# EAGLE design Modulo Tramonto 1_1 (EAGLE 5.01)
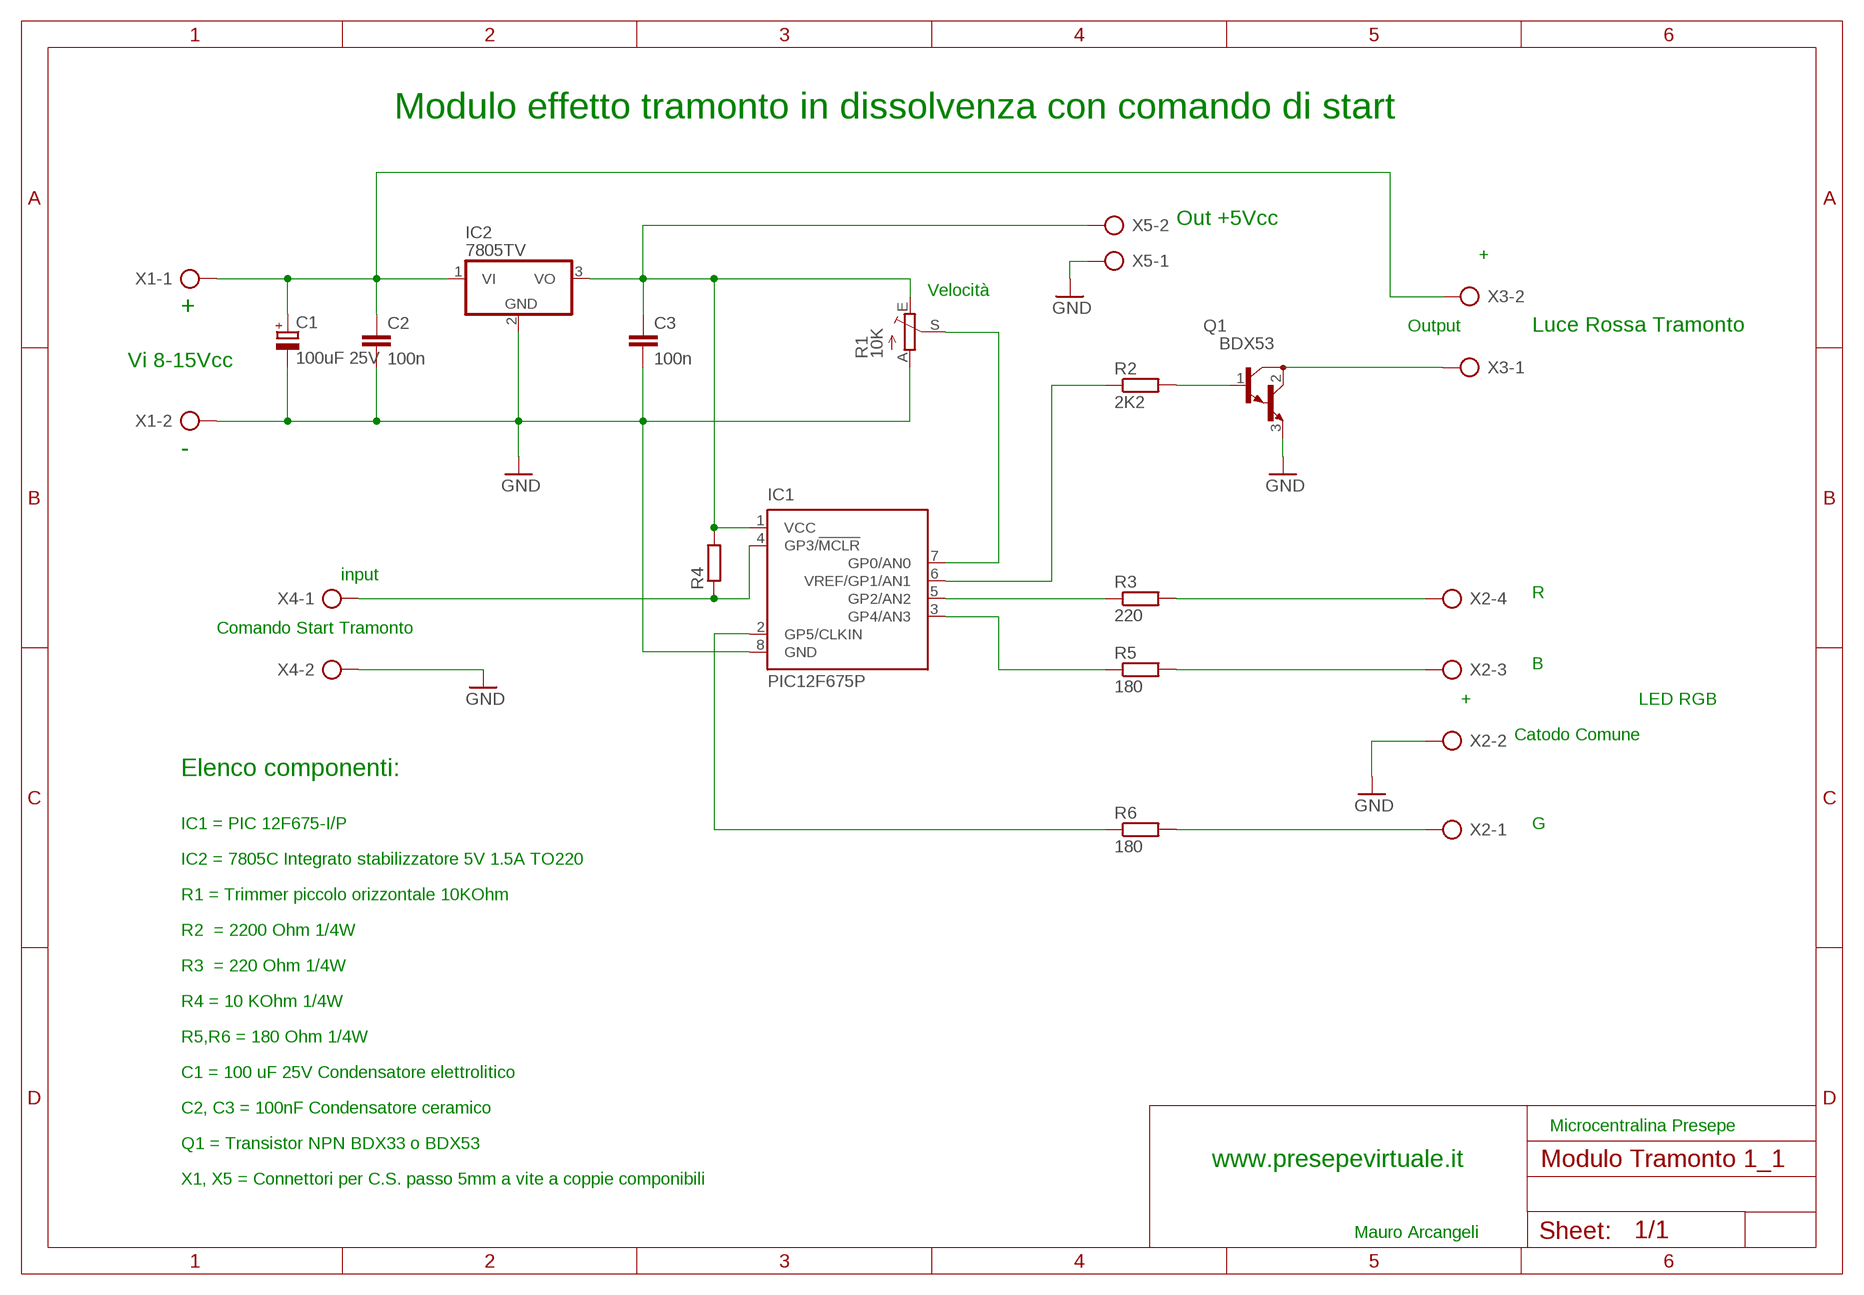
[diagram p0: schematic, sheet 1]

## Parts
C1  100uF 25V  CPOL-EUE5-5  [E5-5]
C2  100n  C-EU050-025X075  [C050-025X075]
C3  100n  C-EU050-025X075  [C050-025X075]
IC1  PIC12F675P  [DIL8]
IC2  7805TV  [TO220V]
Q1  BDX53  [TO220]
R1  10K  TRIM_EU-PT10  [PT-10]
R2  2K2  R-EU_0207/12  [0207/12]
R3  220  R-EU_0207/12  [0207/12]
R4  R-EU_0207/12  [0207/12]
R5  180  R-EU_0207/12  [0207/12]
R6  180  R-EU_0207/12  [0207/12]
X1  AK500/2  [AK500/2]
X2  AK500/4  [AK500/4]
X3  AK500/2  [AK500/2]
X4  AK500/2  [AK500/2]
X5  AK500/2  [AK500/2]

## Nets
GND: C1.- C2.2 C3.2 IC1.8(GND) IC2.2(GND) Q1.3(E) R1.A X1.2 X2.2 X4.2 X5.1
N$1: C1.+ C2.1 IC2.1(VI) X1.1 X3.2
N$2: C3.1 IC1.1(VCC) IC2.3(VO) R1.E R4.2 X5.2
N$3: IC1.2(GP5/CLKIN) R6.1
N$4: Q1.1(B) R2.2
N$5: R3.2 X2.4
N$6: Q1.2(C) X3.1
N$7: IC1.5(GP2/AN2) R3.1
N$8: IC1.7(GP0/AN0) R1.S
N$9: IC1.4(GP3/!MCLR) R4.1 X4.1
N$10: IC1.3(GP4/AN3) R5.1
N$11: R5.2 X2.3
N$12: R6.2 X2.1
N$15: IC1.6(VREF/GP1/AN1) R2.1

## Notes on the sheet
- Modulo effetto tramonto in dissolvenza con comando di start
- Out +5Vcc
- +
- Velocità
- +
- Output | Luce Rossa Tramonto
- Vi 8-15Vcc
- -
- input
- R
- Comando Start Tramonto
- B
- + | LED RGB
- Catodo Comune
- Elenco componenti:
- IC1 = PIC 12F675-I/P | G
- IC2 = 7805C Integrato stabilizzatore 5V 1.5A TO220
- R1 = Trimmer piccolo orizzontale 10KOhm
- R2  = 2200 Ohm 1/4W
- R3  = 220 Ohm 1/4W
- R4 = 10 KOhm 1/4W
- R5,R6 = 180 Ohm 1/4W
- C1 = 100 uF 25V Condensatore elettrolitico
- C2, C3 = 100nF Condensatore ceramico
- Microcentralina Presepe
- Q1 = Transistor NPN BDX33 o BDX53
- www.presepevirtuale.it
- X1, X5 = Connettori per C.S. passo 5mm a vite a coppie componibili
- Mauro Arcangeli

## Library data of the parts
C1 = rcl:CPOL-EU: POLARIZED CAPACITOR, European symbol
C2 C3 = rcl:C-EU: CAPACITOR, European symbol
IC1 = microchip:PIC12F675: 8-Pin FLASH-Based 8-Bit CMOS Microcontroller Precision Internal 4 MHz oscillator factory calibrated to ±1% Low Power Features: Standby Current: - 1 nA @ 2.0V, typical Operating Current: - 8.5&micro;A @ 32 kHz, 2.0V, typical - 100&micro;A @ 1 MHz, 2.0V, typical Watchdog Timer Current: - 300 nA @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
IC2 = linear:78*: Positive VOLTAGE REGULATOR Source: http://cache.national.com/ds/LM/LM78L05.pdf http://www.fairchildsemi.com/ds/LM/LM7805.pdf
Q1 = transistor-npn:BDX53*: NPN Darlington Transistor
R1 = pot:TRIM_EU-: POTENTIOMETER
R2-R6 = rcl:R-EU_: RESISTOR, European symbol
X1 X3-X5 = con-ptr500:AK500/2: CONNECTOR
X2 = con-ptr500:AK500/4: CONNECTOR

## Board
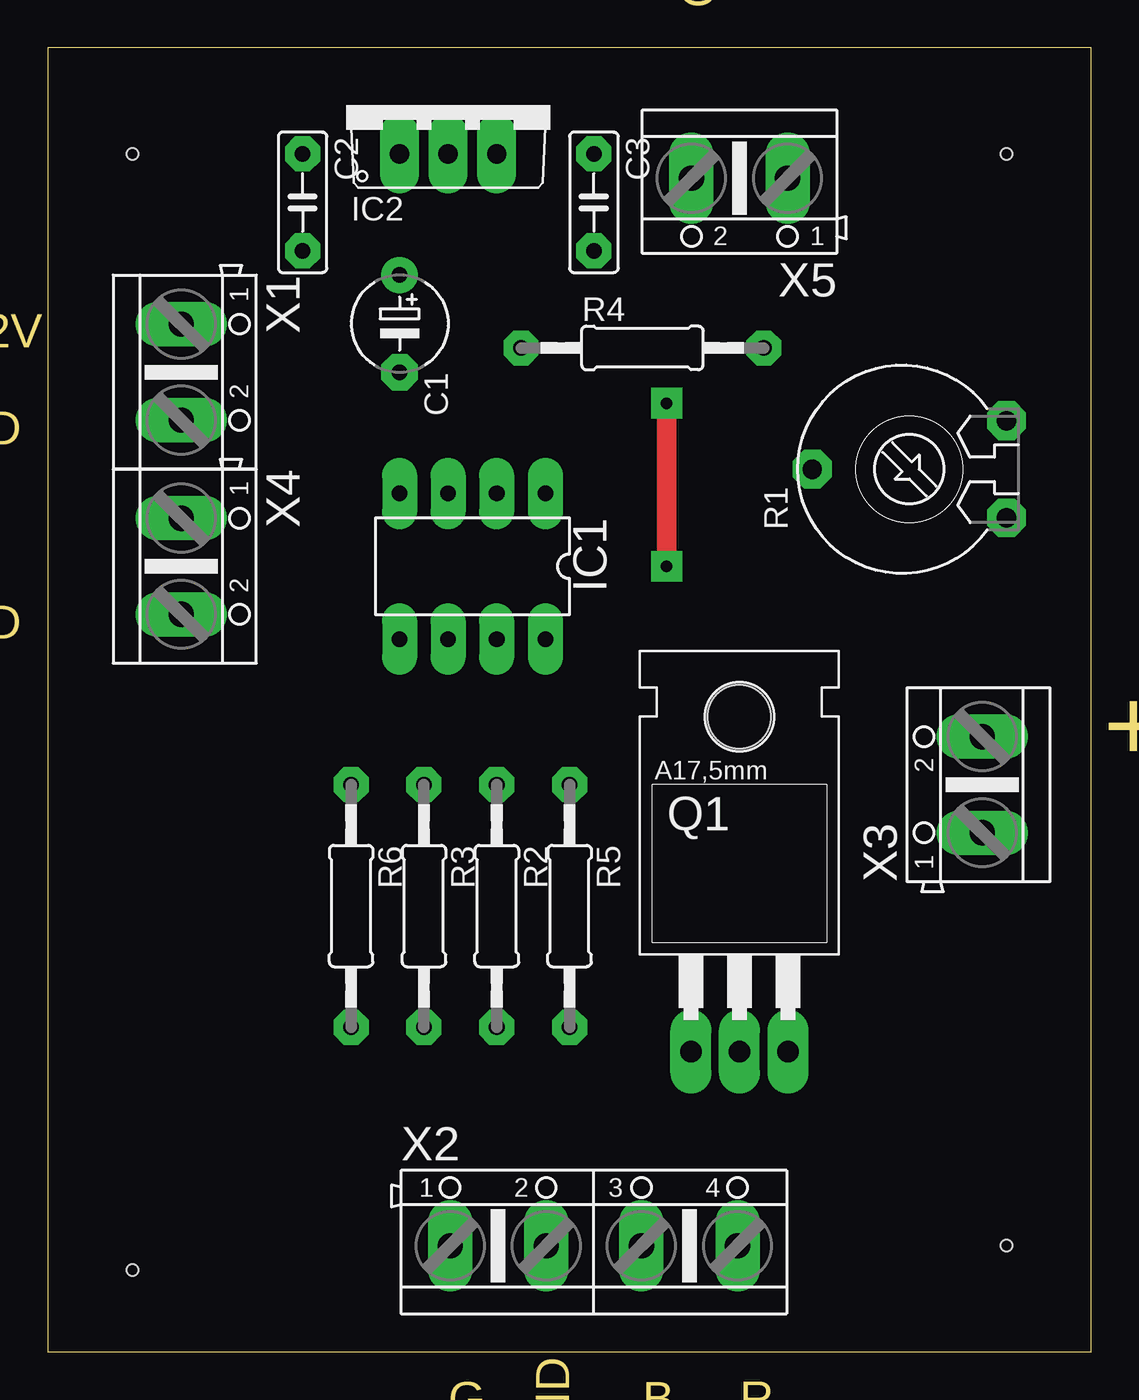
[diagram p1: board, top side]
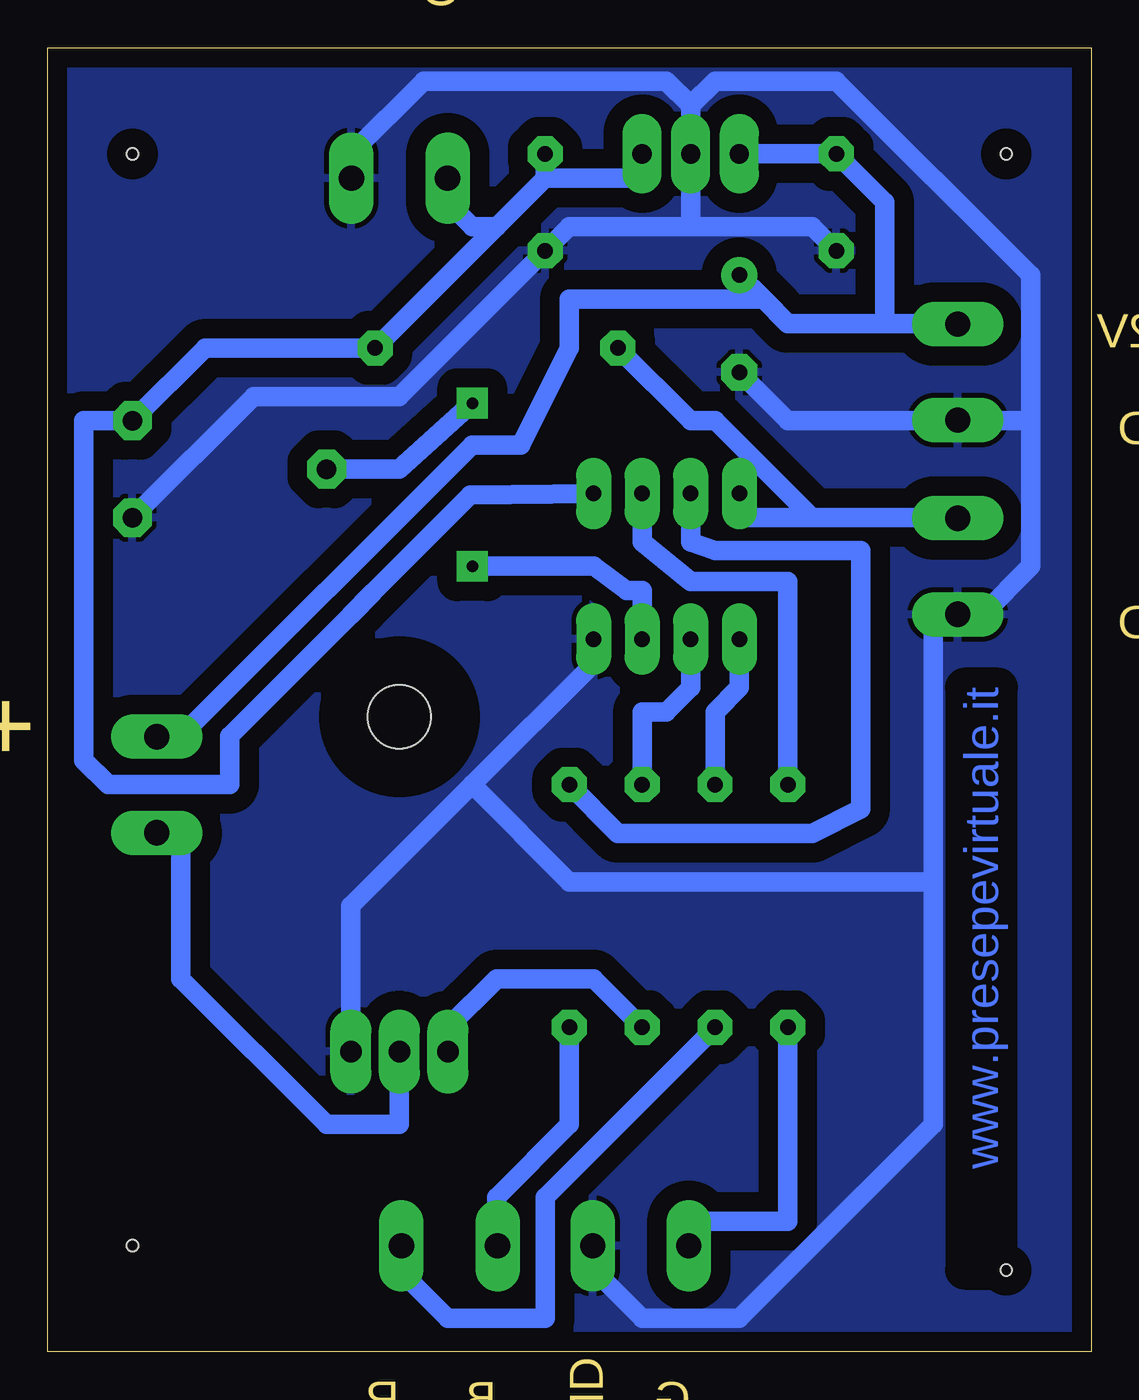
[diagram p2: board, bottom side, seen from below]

Size 54.59 x 68.25 mm. Coordinates in mm from the lower left corner, seen from the top.
Outline: 0,0 54.59,0 54.59,68.25 0,68.25 0,0
Copper layers (1*16): Top 0.035mm / dielectric 1.5mm / Bottom 0.035mm
Design rules "default *": minimum track width 40mil, minimum drill 24mil, track to track 40mil, track to pad 40mil, pad to pad 10mil, via to via 20mil, smd to smd 8mil, copper to edge 40mil, drill to drill 8mil, minimum pad ring 20mil, minimum via ring 20mil, stop-mask expansion 4mil, vias tented up to drill 0mil, thermal gap 10mil
Holes 0.6 mm at 4.44,62.7 50.16,62.7 50.16,5.55 4.44,4.28

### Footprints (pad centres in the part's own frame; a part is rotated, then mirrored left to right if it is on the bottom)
E5-5 = drill 0.813 pad 1.905 round: + -2.54,0 | drill 0.813 pad 1.905 octagon: - 2.54,0
C050-025X075 = drill 0.813 octagon: 1 -2.54,0; 2 2.54,0
DIL8 = drill 0.813 long: 1 -3.81,-3.81; 2 -1.27,-3.81; 3 1.27,-3.81; 4 3.81,-3.81; 5 3.81,3.81; 6 1.27,3.81; 7 -1.27,3.81; 8 -3.81,3.81
TO220V = drill 1.016 long: 1 -2.54,-2.54; 2 0,-2.54; 3 2.54,-2.54
TO220 = drill 1.118 long: 1 -2.54,-6.35; 2 0,-6.35; 3 2.54,-6.35 | hole 3.302: 0,11.176
PT-10 = drill 1.016 octagon: A -2.54,-5.08; E 2.54,-5.08; S 0,5.08
0207/12 = drill 0.813 octagon: 1 -6.35,0; 2 6.35,0
AK500/2 = drill 1.321 long: 1 -2.515,0; 2 2.515,0
AK500/4 = drill 1.321 long: 1 -7.518,0; 2 -2.489,0; 3 2.489,0; 4 7.518,0

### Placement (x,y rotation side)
C1  18.41,53.81 270 top
C2  13.33,60.16 270 top
C3  28.57,60.16 270 top
IC1  22.22,41.11 180 top
IC2  20.95,65.24 0 top
Q1  36.19,22.06 0 top
R1  45.08,46.19 90 top
R2  23.49,23.33 270 top
R3  19.68,23.33 270 top
R4  31.11,52.54 0 top
R5  27.3,23.33 270 top
R6  15.87,23.33 270 top
X1  6.98,51.27 270 top
X2  28.57,5.55 0 top
X3  48.89,29.68 90 top
X4  6.98,41.11 270 top
X5  36.19,61.43 180 top

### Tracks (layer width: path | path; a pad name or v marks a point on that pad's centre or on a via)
GND
  Bottom 1.016: C2.2 14.6,58.89 20.95,58.89 | 20.95,58.89 27.3,58.89 C3.2 36.19,50 43.81,50 R1.A | 20.95,58.89 IC2.2 20.95,65.24 | 20.95,65.24 22.22,66.51 34.92,66.51 38.73,62.7 X5.1 | 32.38,29.68 38.73,23.33 Q1.3 | 32.38,29.68 26.03,36.03 IC1.8 | C1.- 15.87,48.73 8.25,48.73 X1.2 5.71,48.73 3.17,48.73 | 3.17,48.73 3.17,41.11 5.71,38.57 X4.2 8.25,38.57 8.25,24.6 | 8.25,24.6 8.25,11.9 18.41,1.74 23.49,1.74 26.03,4.28 X2.2 | 32.38,29.68 27.3,24.6 8.25,24.6 | 20.95,65.24 19.68,66.51 13.33,66.51 3.17,56.35 3.17,48.73
  pour Bottom: 0.63,67.78 53.97,67.78 53.97,0.47 0.63,0.47
N$1
  Bottom 1.016: IC2.1 C2.1 10.79,60.16 10.79,53.81 | 17.14,55.08 15.87,53.81 10.79,53.81 | 17.14,55.08 C1.+ | 10.79,53.81 8.25,53.81 X1.1 | 17.14,55.08 27.3,55.08 27.3,52.54 29.84,47.46 32.38,47.46 47.62,32.22 X3.2
N$2
  Bottom 1.016: 31.11,58.89 28.57,61.43 | 31.11,58.89 R4.2 46.35,52.54 R1.E 52.7,48.73 52.7,30.95 51.43,29.68 45.08,29.68 45.08,32.22 38.73,38.57 37.58,39.75 32.5,44.83 IC1.1 | 28.57,61.43 23.49,61.43 IC2.3 | 28.57,61.43 C3.1 | 31.11,58.89 32.38,58.89 33.65,60.16 X5.2
N$3
  Bottom 1.016: IC1.2 23.49,42.38 20.95,40.31 15.87,40.31 R6.1
N$4
  Bottom 1.016: R2.2 26.03,19.52 31.11,19.52 33.65,16.98 Q1.1
N$5
  Bottom 1.016: R3.2 28.57,8.09 28.57,1.74 33.65,1.74 36.19,4.28 X2.4
N$6
  Bottom 1.016: Q1.2 36.19,11.9 40,11.9 47.62,19.52 47.62,27.14 X3.1
N$7
  Bottom 1.016: R3.1 19.68,33.49 18.41,34.76 IC1.5
N$8  (via drill 0.6)
  Top 1.016: v32.38,41.11 v32.38,49.65
  Bottom 1.016: IC1.7 23.49,39.84 24.29,39.84 26.03,41.11 v32.38,41.11 | v32.38,49.65 36.19,46.19 R1.S
N$9
  Bottom 1.016: 14.6,43.65 8.25,43.65 X4.1 | 14.6,43.65 18.41,43.65 IC1.4 | R4.1 20.95,48.73 19.68,48.73 14.6,43.65
N$10
  Bottom 1.016: R5.1 24.76,27.14 14.6,27.14 12.06,28.41 12.06,41.93 19.68,41.93 20.95,42.38 IC1.3
N$11
  Bottom 1.016: R5.2 27.3,11.9 31.11,8.09 31.11,6.82 X2.3
N$12
  Bottom 1.016: R6.2 15.87,6.82 20.95,6.82 X2.1
N$15
  Bottom 1.016: R2.1 23.49,33.49 22.22,33.49 20.95,34.76 IC1.6

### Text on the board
Bottom: www.presepevirtuale.it
Dimension: GND | OUT +5V | Alimentazione +8/12V | GND | + | GND | + | Lampada tramonto | G | B | R | GND | LED RGB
